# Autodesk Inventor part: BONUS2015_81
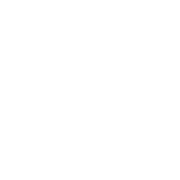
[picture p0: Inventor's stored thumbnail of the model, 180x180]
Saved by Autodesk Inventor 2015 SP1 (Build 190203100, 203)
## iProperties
Created: 2015-05
Part Number: BONUS2015_81
Material: Generisch
Document SubType Name: Modeling
Density: 1 g/cm^3
Appearance: Vorgabe
xx: 81
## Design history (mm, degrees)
